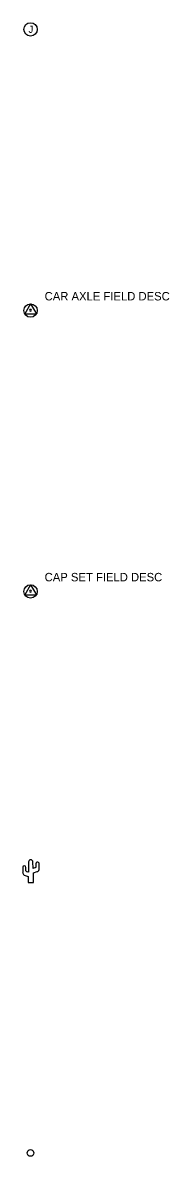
# Model space of a CAD drawing. Extents: x 98 to 2902, y -6 to 903.
# Drawn here: x 298.6 to 324.7, y 199.4 to 401.2 of the extents above; entities that cross this region are included whole.
import ezdxf

# ---------------------------------------------------------------- set-up
doc = ezdxf.new("R2010")
doc.units = 0
for name, color, linetype in [('V-COMM-JBOX', 7, 'Continuous'), ('V-POWR-POLE', 7, 'Continuous'), ('V-SITE-VEGE', 7, 'Continuous'), ('V-SURV-DATA', 7, 'Continuous')]:
    doc.layers.add(name, color=color, linetype=linetype)

msp = doc.modelspace()

# ---------------------------------------------------------------- linework, layer by layer
at = {"layer": 'V-COMM-JBOX'}
msp.add_circle((300, 400), 1.19, dxfattribs=at)
at = {"layer": 'V-POWR-POLE'}
msp.add_circle((300, 200), 0.595, dxfattribs=at)
at = {"layer": 'V-SITE-VEGE'}
for p, q in [((298.59, 250.86), (298.59, 249.93)), ((299.15, 250.24), (299.15, 250.84)), ((300.96, 251.48), (300.95, 250.9)), ((301.53, 250.44), (301.53, 251.4))]:
    msp.add_line(p, q, dxfattribs=at)
for points in [[(299.65, 251.83), (299.6, 250), (299.4, 250.02)], [(300.89, 250.79), (300.45, 250.63), (300.41, 251.82)], [(298.85, 249.47), (299.54, 249.24), (299.54, 248.13)], [(299.54, 248.13), (300.52, 248.13), (300.52, 249.88), (301.17, 250.08)]]:
    msp.add_lwpolyline(points, dxfattribs=at)
for centre, radius, start, end in [((298.87, 250.82), 0.282, 4.7696, 171.4411), ((299.43, 250.3), 0.28, 192.6347, 264.8121), ((300.03, 251.81), 0.38, 1.8759, 177.6122), ((300.78, 250.91), 0.168, 310.2413, 354.9718), ((301.25, 251.48), 0.289, 343.5909, 180.8436), ((301.14, 250.47), 0.389, 273.6093, 355.5958), ((299.07, 249.9), 0.483, 176.8162, 242.7055)]:
    msp.add_arc(centre, radius, start, end, dxfattribs=at)
at = {"layer": 'V-SURV-DATA'}
for p, q in [((300, 351.14), (298.97, 349.35)), ((300, 351.14), (301.03, 349.35)), ((298.97, 349.35), (301.03, 349.35)), ((300, 301.14), (298.97, 299.35)), ((300, 301.14), (301.03, 299.35)), ((298.97, 299.35), (301.03, 299.35))]:
    msp.add_line(p, q, dxfattribs=at)
for centre in [(300, 349.95), (300, 299.95)]:
    msp.add_circle(centre, 1.19, dxfattribs=at)
for centre in [(300, 350), (300, 300)]:
    msp.add_arc(centre, 0.165, 92.2877, 90.5674, dxfattribs=at)

# ---------------------------------------------------------------- texts
at = {"layer": 'V-COMM-JBOX'}
msp.add_text('J', height=1.25, dxfattribs=at).set_placement((299.63, 399.38))
at = {"layer": 'V-SURV-DATA'}
for s, p in [('CAR AXLE FIELD DESC', (302.5, 351.75)), ('CAP SET FIELD DESC', (302.5, 301.75))]:
    msp.add_text(s, height=1.5, dxfattribs=at).set_placement(p)

doc.saveas('drawing.dxf')
